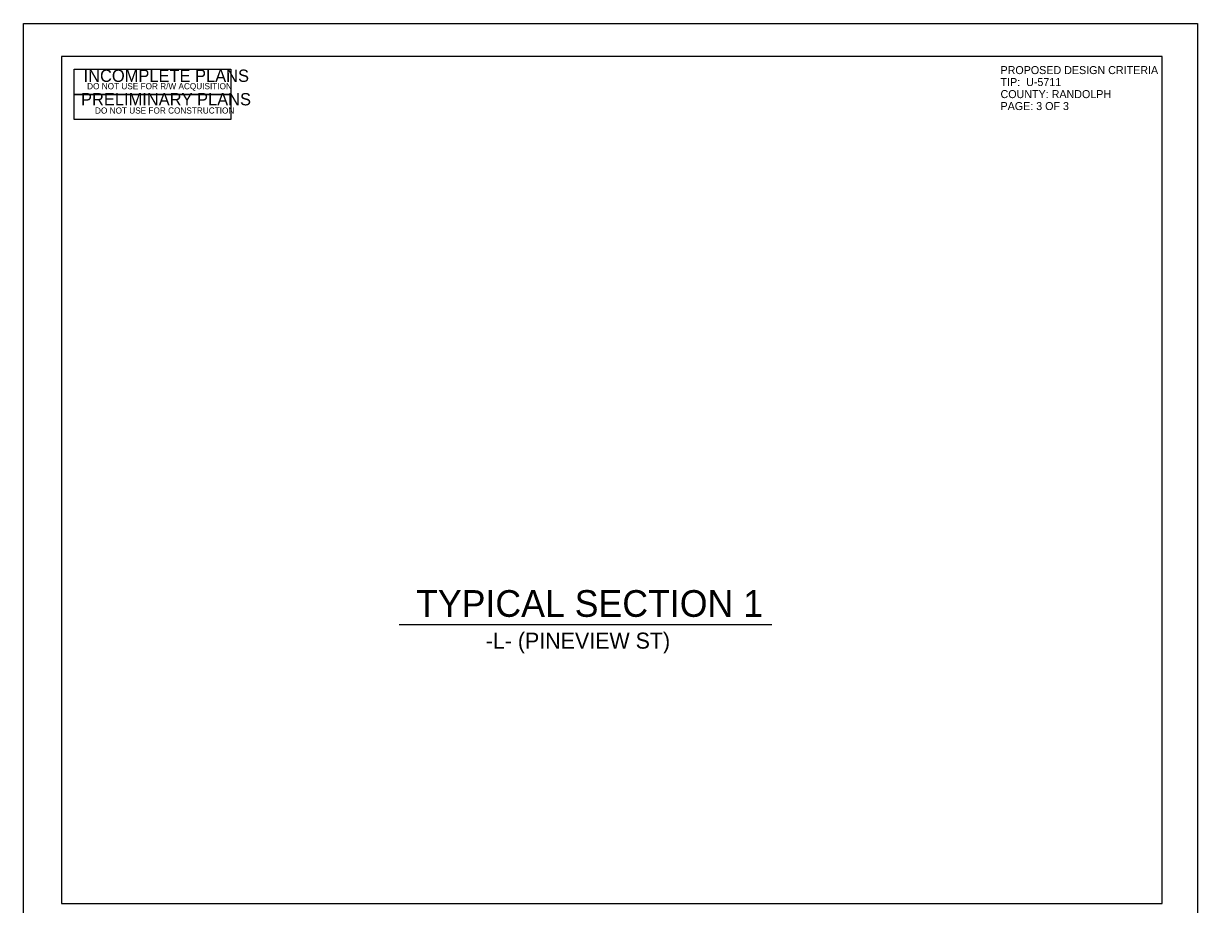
# Model space of a CAD drawing. Extents: x 1901718 to 1902220, y 193828 to 194187.
# Drawn here: x 1901718.5 to 1901828.5, y 194104.8 to 194187.3 of the extents above; entities that cross this region are included whole.
import ezdxf

# ---------------------------------------------------------------- set-up
doc = ezdxf.new("R2010")
doc.units = 0
for name, color, linetype in [('Old_Level_1', 7, 'Continuous'), ('Old_Level_10', 7, 'Continuous'), ('Prop Dimension Text', 7, 'Continuous'), ('Scratch_Level_0', 7, 'Continuous'), ('Sheet Sticker Incomplete CELL', 7, 'Continuous'), ('Sheet Sticker Preliminary CELL', 7, 'Continuous')]:
    doc.layers.add(name, color=color, linetype=linetype)

msp = doc.modelspace()

# ---------------------------------------------------------------- linework, layer by layer
at = {"layer": 'Old_Level_1'}
msp.add_line((1901753.68, 194131), (1901788.58, 194131), dxfattribs=at)
at = {"layer": 'Old_Level_10'}
msp.add_lwpolyline([(1901722.03, 194104.87), (1901825.15, 194104.87), (1901825.15, 194184.21), (1901722.03, 194184.21)], close=True, dxfattribs=at)
at = {"layer": 'Scratch_Level_0'}
msp.add_lwpolyline([(1901718.48, 194187.31), (1901828.48, 194187.31), (1901828.48, 194102.31), (1901718.48, 194102.31)], close=True, dxfattribs=at)
at = {"layer": 'Sheet Sticker Incomplete CELL'}
msp.add_lwpolyline([(1901723.22, 194180.67), (1901723.22, 194183.02), (1901737.92, 194183.02), (1901737.92, 194180.67)], close=True, dxfattribs=at)
at = {"layer": 'Sheet Sticker Preliminary CELL'}
msp.add_lwpolyline([(1901723.22, 194178.32), (1901723.22, 194180.67), (1901737.92, 194180.67), (1901737.92, 194178.32)], close=True, dxfattribs=at)

# ---------------------------------------------------------------- texts
at = {"layer": 'Old_Level_1'}
for s, height, p in [('PROPOSED DESIGN CRITERIA', 0.75, (1901810.02, 194182.57)), ('TIP:  U-5711', 0.75, (1901810.02, 194181.45)), ('COUNTY: RANDOLPH', 0.75, (1901810.02, 194180.32)), ('PAGE: 3 OF 3', 0.75, (1901810.02, 194179.2)), ('TYPICAL SECTION 1', 2.5, (1901755.26, 194131.73))]:
    msp.add_text(s, height=height, dxfattribs=at).set_placement(p)
at = {"layer": 'Prop Dimension Text'}
msp.add_text('-L- (PINEVIEW ST) ', height=1.5, dxfattribs=at).set_placement((1901761.79, 194128.75))
at = {"layer": 'Sheet Sticker Incomplete CELL'}
for s, height, p in [('INCOMPLETE PLANS', 1.152, (1901724.11, 194181.84)), ('DO NOT USE FOR R/W ACQUISITION', 0.576, (1901724.44, 194181.15))]:
    msp.add_text(s, height=height, dxfattribs=at).set_placement(p)
at = {"layer": 'Sheet Sticker Preliminary CELL'}
for s, height, p in [('PRELIMINARY PLANS', 1.152, (1901723.87, 194179.64)), ('DO NOT USE FOR CONSTRUCTION', 0.576, (1901725.18, 194178.87))]:
    msp.add_text(s, height=height, dxfattribs=at).set_placement(p)

doc.saveas('drawing.dxf')
